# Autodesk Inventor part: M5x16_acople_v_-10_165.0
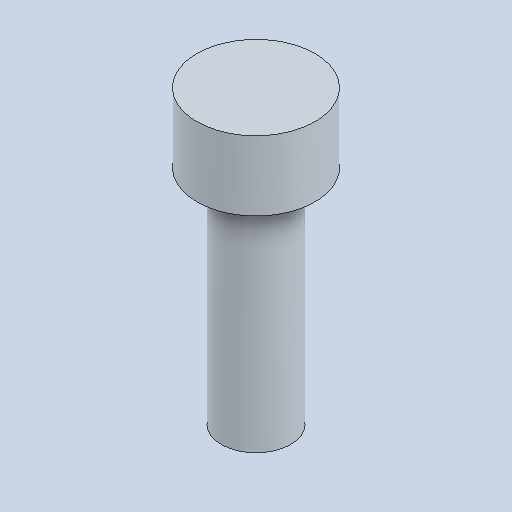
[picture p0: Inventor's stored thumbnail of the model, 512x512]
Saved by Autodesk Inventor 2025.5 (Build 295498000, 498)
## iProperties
Created: 2026-10
Part Number: M5x16_acople_v_-10_165.0
Material: Genérico
Document SubType Name: Modeling
Designer: Luis M
Density: 1 g/cm^3
Appearance: Valor por defecto
Author: Luis M
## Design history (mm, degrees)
feature "Base1"
node "Sólido1"
